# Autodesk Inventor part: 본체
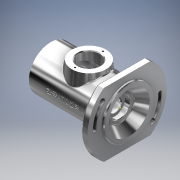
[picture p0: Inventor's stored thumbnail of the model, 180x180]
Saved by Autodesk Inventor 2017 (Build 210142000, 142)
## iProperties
Part Number: 본체
Material: 알루미늄 6061
Document SubType Name: Modeling
Designer: MRC
Density: 2.7 g/cm^3
Appearance: 알루미늄 - 평지
Mass: 686.809 g
Surface Area: 618.883 cm^2
Volume: 254.374 cm^3
Author: MRC
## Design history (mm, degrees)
sketch "스케치1"
  geometry: L1 (47, 33.985)-(47, -33.985); L2 (-47, 33.985)-(-47, -33.985); A1 r 58 centre (0, 0) between (47, 33.985) and (-47, 33.985); A2 r 58 centre (0, 0) between (-47, -33.985) and (47, -33.985); 1 further point
  constraints: 4 end point, 4 point on circle, 2 centre point, 2 vertical, 1 coincident
  dimensions: "d1" = 47 distance from line of point (0, 0) L1; "d2" = 47 distance from line of point (0, 0) L2; "d3" = 58 radius of A2; "d4" = 58 radius of A1
extrude "돌출1" new body sketch "스케치1" distance "d5" = 10; taper "d6" = 0 deg
sketch "스케치2"
  geometry: C1 r 32 at (0, 0); 1 further point
  constraints: 1 centre point, 1 coincident
  dimensions: "d7" = 64 diameter of C1
extrude "돌출2" join sketch "스케치2" distance "d8" = 102; taper "d9" = 0 deg
node "작업 평면1"
sketch "스케치3"
  geometry: L1 (0, 33.985)-(0, -33.985) reference; L2 (102, -32)-(102, 32) reference; C1 r 25 at (46, 0); 2 further points
  constraints: 1 centre point, 1 horizontal alignment, 1 midpoint
  dimensions: "d11" = 50 diameter of C1; "d12" = 56 distance from line of C1.centre L2
extrude "돌출3" join sketch "스케치3" stored distance "d13" = 102; taper "d14" = 5 deg
sketch "스케치4"
  geometry: C1 r 37 at (0, 0); 1 further point
  constraints: 1 centre point, 1 coincident
  dimensions: "d15" = 74 diameter of C1
extrude "돌출4" join sketch "스케치4" distance "d16" = 3; taper "d17" = 0 deg
sketch "스케치5"
  geometry: L1 (-102, 32)-(-102, -32) reference; L2 (-102, 0)-(13, 0); L3 (13, -37)-(13, 37) reference; L4 (-102, 0)-(-102, 22.5); L5 (-102, 22.5)-(-94, 22.5); L6 (-94, 22.5)-(-94, 24); L7 (-94, 24)-(-91, 24); L8 (-91, 24)-(-91, 22.5); L9 (-91, 22.5)-(-80, 22.5); L10 (-80, 22.5)-(-80, 17.5); L11 (-80, 17.5)-(-77.75, 17.5); L12 (-76, 17.5)-(-76, 18.5); L13 (-77.75, 18.5)-(-77.75, 17.5); L14 (-76, 17.5)-(-65, 17.5); L15 (-65, 17.5)-(-65, 27); L16 (-65, 27)-(-27, 27); L17 (-27, 27)-(-27, 17.5); L18 (-27, 17.5)-(-16, 17.5); L19 (-16, 17.5)-(-16, 15); L20 (-16, 15)-(-11, 15); L21 (-11, 15)-(-11, 11); L22 (-11, 11)-(-8.3, 11); L23 (-8.3, 11)-(-8.3, 15); L24 (-1, 15)-(-1, 20); L25 (-1, 20)-(13, 30); L26 (13, 30)-(13, 0); L27 (-76, 18.5)-(-77.75, 18.5); L28 (-8.3, 15)-(-1, 15); 1 further point
  constraints: 52 end point, 15 perpendicular, 5 point on line, 3 horizontal, 2 midpoint, 1 parallel
  dimensions: "d18" = 45 diameter of L5 L2; "d19" = 48 diameter of L7 L2; "d20" = 45 diameter of L9 L2; "d21" = 37 diameter of L27 L2; "d22" = 35 diameter of L11 L2; "d23" = 54 diameter of L16 L2; "d24" = 30 diameter of L20 L2; "d25" = 22 diameter of L22 L2; "d26" = 30 diameter of L28 L2; "d27" = 40 diameter of L24.end L2; "d28" = 60 diameter of L25.end L2; "d29" = 8 distance of L4.end L5.end; "d30" = 3 distance of L6.end L7.end; "d31" = 22 distance between parallel lines of L10 L4; "d33" = 38 distance of L15.end L16.end; "d34" = 11 distance of L17.end L18.end; "d35" = 5 distance of L19.end L20.end; "d36" = 14 horizontal distance of L24.end L25.end; "d38" = 1.75 distance of L12.end L13.start; "d39" = 7.3 distance of L23.end L24.start; "d128" = 4 distance between parallel lines of L12 L10; "d129" = 11 distance of L12.start L14.end; "d130" = 2.25 distance of L10.end L11.end
revolve "회전1" sketch "스케치5" stored, may be unused: angle "d40" = 90 deg
sketch "스케치6"
  geometry: 1 further point
feature "스레드1" dims "d41" = 10, "d42" = 0
sketch "스케치7"
  geometry: C1 r 25 at (0, 0) reference; C2 r 16 at (0, 0); 1 further point
  constraints: 1 centre point, 1 coincident
  dimensions: "d43" = 32 diameter of C2
extrude "돌출5" cut sketch "스케치7" distance "d44" = 30; taper "d45" = 0 deg
sketch "스케치8"
  geometry: L1 (0, 0)-(36.77, 30.854); L2 (0, 0)-(48, 0); L3 (0, 0)-(-36.77, -30.854); A1 r 48 centre (0, 0) between (36.77, 30.854) and (48, 0); A2 r 4 centre (36.77, 30.854) between (40.58, 29.636) and (37.033, 26.862); A3 r 4 centre (-36.77, -30.854) between (-40.58, -29.636) and (-37.033, -26.862); A4 r 2.25 centre (-48, 0) between (-45.75, 0) and (-50.25, 0); A5 r 4 centre (-48, 0) between (-44, 0) and (-52, 0); A6 r 4 centre (48, 0) between (44, 0) and (52, 0); A7 r 2.25 centre (48, 0) between (45.75, 0) and (50.25, 0); A8 r 52 centre (0, 0) between (52, 0) and (39.834, 33.425); A9 r 52 centre (0, 0) between (-52, 0) and (-39.834, -33.425); A10 r 50.25 centre (0, 0) between (50.25, 0) and (40.58, 29.636); A11 r 50.25 centre (0, 0) between (-50.25, 0) and (-40.58, -29.636); A12 r 45.75 centre (0, 0) between (45.75, 0) and (37.033, 26.862); A13 r 45.75 centre (0, 0) between (-45.75, 0) and (-37.033, -26.862); A14 r 44 centre (0, 0) between (44, 0) and (33.706, 28.283); A15 r 44 centre (0, 0) between (-44, 0) and (-33.706, -28.283); 1 further point
  constraints: 36 point on circle, 15 centre point, 6 coincident, 6 end point, 1 collinear, 1 horizontal, 1 horizontal alignment
  dimensions: "d46" = 96 diameter of A1; "d47" = 40 deg angle of L2 L1; "d48" = 8 diameter of A2; "d49" = 8 diameter of A3; "d72" = 4.5 diameter of A4; "d73" = 8 diameter of A5; "d74" = 8 diameter of A6; "d75" = 4.5 diameter of A7; "d76" = 52 radius of A8; "d77" = 50.25 radius of A10; "d78" = 45.75 radius of A12; "d79" = 44 radius of A14; "d80" = 44 radius of A15; "d81" = 45.75 radius of A13; "d82" = 50.25 radius of A11; "d83" = 52 radius of A9
extrude "돌출7" cut sketch "스케치8" distance "d84" = 4.4; taper "d85" = 0 deg
sketch "스케치10"
  geometry: L1 (-58, 0)-(57.839, 0); L2 (36.77, 30.854)-(0, 0); L3 (0, 0)-(-36.77, -30.854); C1 r 4 at (-36.77, -30.854); C2 r 4 at (36.77, 30.854); A1 r 58 centre (0, 0) between (-33.985, 47) and (-33.985, -47) reference; A2 r 48 centre (0, 0) between (-36.77, -30.854) and (36.77, 30.854); 1 further point
  constraints: 6 end point, 3 centre point, 3 point on circle, 1 coincident, 1 horizontal, 1 point on line
  dimensions: "d86" = 8 diameter of C1; "d87" = 8 diameter of C2; "d88" = 40 deg angle of L1 L2; "d89" = 40 deg angle of L1 L3; "d90" = 96 diameter of A2
extrude "돌출8" cut sketch "스케치10" stored distance "d91" = 4.4; taper "d92" = 0 deg
extrude "돌출9" cut sketch "스케치8" stored distance "d93" = 4.4; taper "d94" = 0 deg
sketch "스케치11"
  geometry: C1 r 16 at (0, 0) reference; A1 r 20.5 centre (0, 0) between (0, 20.5) and (0, -20.5); 1 further point
  constraints: 2 point on circle, 2 vertical alignment, 1 centre point, 1 coincident
  dimensions: "d95" = 41 diameter of A1
hole "구멍1" sketch "스케치11" at (0, 20.5), (0, -20.5) diameter "d96" = 2.459; stored, may be unused: countersink angle "d100" = 90 deg, drill point angle "d102" = 118 deg; dims "d97" = 6, "d98" = 4, "d99" = 2, "d101" = 8
fillet "모깎기1" dims "d103" = 3
fillet "모깎기2" dims "d104" = 3
fillet "모깎기3" dims "d105" = 3
fillet "모깎기4" dims "d106" = 3
fillet "모깎기5" dims "d107" = 0.6
fillet "모깎기6" dims "d108" = 0.5
chamfer "모따기1" distance "d109" = 0.7; stored, may be unused: second distance "d110" = 2, angle "d111" = 30 deg
chamfer "모따기2" distance "d112" = 1; stored, may be unused: second distance "d113" = 2, angle "d114" = 30 deg
chamfer "모따기3" distance "d115" = 1; stored, may be unused: second distance "d116" = 2, angle "d117" = 30 deg
fillet "모깎기7" dims "d121" = 3
fillet "모깎기8" dims "d122" = 3
fillet "모깎기9" dims "d123" = 3
node "작업 평면2"
sketch "스케치12"
  geometry: L1 (10, -46.4)-(10, 46.4) reference; L2 (0, -44)-(0, 44) reference; 3 further points
  constraints: 1 horizontal alignment, 1 midpoint, 1 other
  dimensions: "d125" = 62 distance from line of L1 point (-52, 0)
feature "엠보싱1" sketch "스케치12" dims "d1" = 47, "d2" = 47, "d3" = 58, "d4" = 58, "d126" = 0.5, "d127" = 0
chamfer "모따기5" distance "d131" = 1; stored, may be unused: second distance "d132" = 2, angle "d133" = 30 deg
node "솔리드1"
other parameters: "d0" = 116, "d10" = 38, "d53" = 2.25, "d54" = 2.25, "d57" = 4, "d58" = 4, "d60" = 8, "d68" = 4, "d69" = 4, "d70" = 2.25, "d71" = 2.25, "d124" = 42
